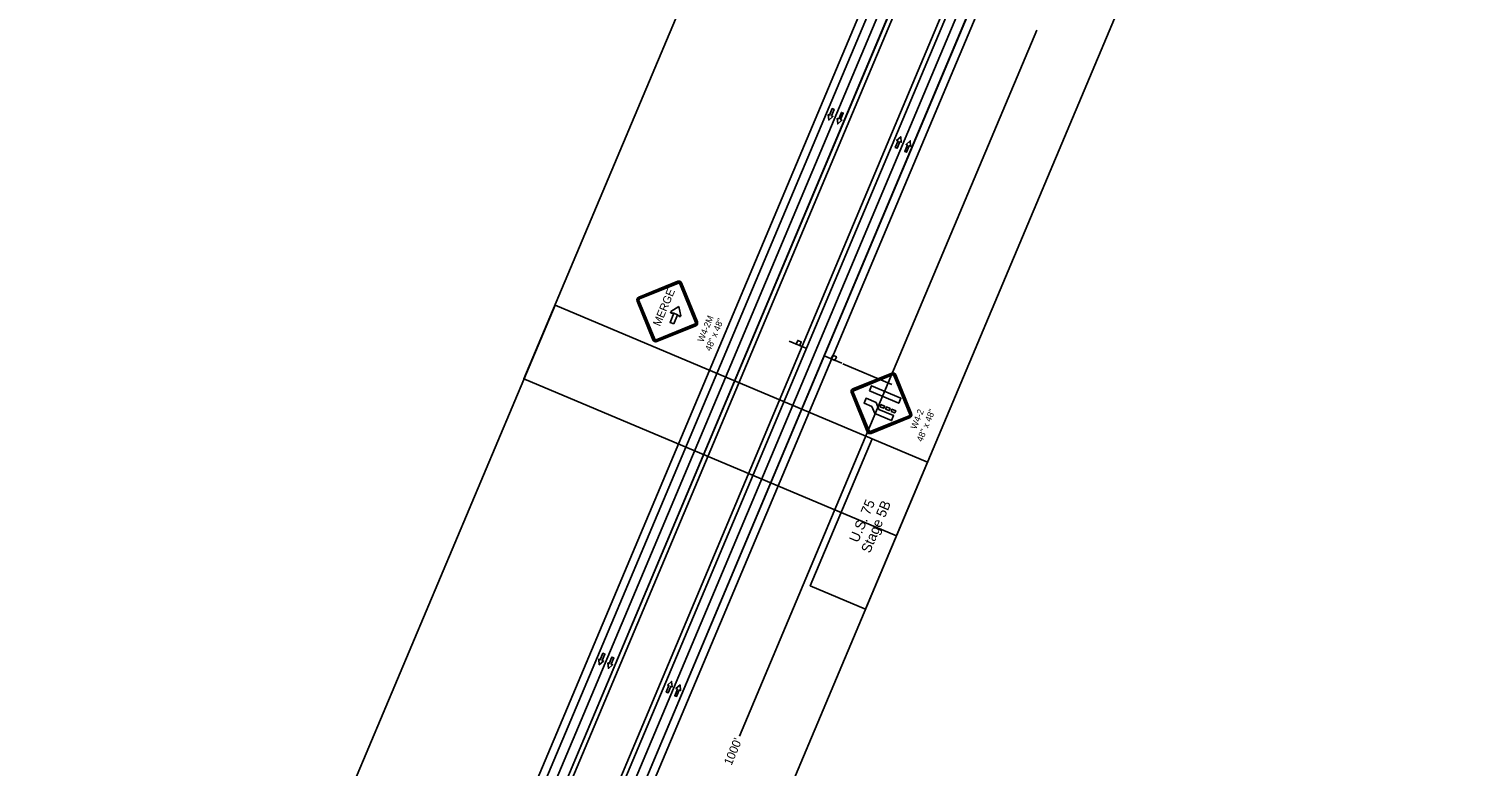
# Model space of a CAD drawing. Extents: x 14104283 to 14128447, y 8633203 to 8671666.
# Drawn here: x 14116868 to 14118675, y 8665326 to 8666247 of the extents above; entities that cross this region are included whole.
import ezdxf

# ---------------------------------------------------------------- set-up
doc = ezdxf.new("R2010")
doc.units = 0
for name, color, linetype in [('Cell', 7, 'Continuous'), ('Default', 7, 'Continuous'), ('dsnNonPlotable', 7, 'Continuous'), ('dsnPaintExistingBrokenLaneLineWhite', 7, 'Continuous'), ('dsnPaintExistingEdgeLineLeftYellow', 7, 'Continuous'), ('dsnPaintExistingEdgeLineRightWhite', 7, 'Continuous'), ('dsnShadingPaved', 7, 'Continuous'), ('dsnStdLabel', 7, 'Continuous'), ('dsnStgShadingPrevPav', 7, 'Continuous'), ('dsnTextOverlapEven', 7, 'Continuous')]:
    doc.layers.add(name, color=color, linetype=linetype)

msp = doc.modelspace()

# ---------------------------------------------------------------- linework, layer by layer
at = {"layer": 'Cell'}
for p, q in [((14117678.8, 8665931.5), (14117630.2, 8665911.7)), ((14117679.2, 8665930.6), (14117679.8, 8665929.2)), ((14117681.4, 8665928.5), (14117682.8, 8665929.1)), ((14117703.5, 8665880.8), (14117683.7, 8665929.4)), ((14117628.1, 8665906.8), (14117647.9, 8665858.2)), ((14117629, 8665907.2), (14117630.4, 8665907.7)), ((14117631.1, 8665909.4), (14117630.5, 8665910.8)), ((14117671, 8665892.7), (14117670.4, 8665893.6)), ((14117670.9, 8665891.7), (14117671, 8665892.7)), ((14117681.6, 8665888.3), (14117680.9, 8665887.5)), ((14117682.6, 8665888.4), (14117681.6, 8665888.3)), ((14117700.5, 8665878.2), (14117701.1, 8665876.8)), ((14117702.6, 8665880.5), (14117701.2, 8665879.9)), ((14117652.8, 8665856.1), (14117701.4, 8665875.9)), ((14117650.2, 8665859.1), (14117648.8, 8665858.5)), ((14117652.5, 8665857), (14117651.9, 8665858.4)), ((14117840.1, 8665847.4), (14117818, 8665856.7)), ((14117883.8, 8665829), (14117861.7, 8665838.3)), ((14117897.8, 8665797), (14117946.5, 8665816.8)), ((14117946.5, 8665816.8), (14117897.8, 8665797)), ((14117898.2, 8665796.2), (14117946.8, 8665816)), ((14117947.4, 8665814.5), (14117898.8, 8665794.7)), ((14117968.8, 8665765.2), (14117949, 8665813.8)), ((14117950.5, 8665814.4), (14117970.3, 8665765.8)), ((14117951.3, 8665814.8), (14117971.1, 8665766.2)), ((14117971.1, 8665766.2), (14117951.3, 8665814.8)), ((14117915.6, 8665743.5), (14117895.8, 8665792.2)), ((14117895.8, 8665792.2), (14117915.6, 8665743.5)), ((14117895.8, 8665792.2), (14117895.8, 8665792.2)), ((14117916.4, 8665743.9), (14117896.6, 8665792.5)), ((14117898.1, 8665793.1), (14117898.1, 8665793.1)), ((14117898.1, 8665793.1), (14117917.9, 8665744.5)), ((14117919.5, 8665743.8), (14117968.1, 8665763.6)), ((14117968.7, 8665762.1), (14117920.1, 8665742.3)), ((14117969.1, 8665761.3), (14117920.5, 8665741.5)), ((14117920.5, 8665741.5), (14117969.1, 8665761.3))]:
    msp.add_line(p, q, dxfattribs=at)
for points in [[(14117872, 8666147.3), (14117874.3, 8666146.3), (14117871, 8666138.2), (14117872.7, 8666137.5), (14117867.5, 8666132.9), (14117867, 8666139.9), (14117868.7, 8666139.2)], [(14117883.3, 8666142.5), (14117885.6, 8666141.6), (14117882.3, 8666133.5), (14117884, 8666132.7), (14117878.8, 8666128.2), (14117878.2, 8666135.1), (14117880, 8666134.4)], [(14117953.1, 8666097.8), (14117950.7, 8666098.7), (14117954.1, 8666106.8), (14117952.3, 8666107.6), (14117957.6, 8666112.1), (14117958.1, 8666105.2), (14117956.4, 8666105.9)], [(14117964.9, 8666092.8), (14117962.5, 8666093.8), (14117965.9, 8666101.9), (14117964.1, 8666102.6), (14117969.4, 8666107.2), (14117969.9, 8666100.2), (14117968.2, 8666100.9)], [(14117679.2, 8665930.6), (14117630.5, 8665910.8), (14117631.1, 8665909.4), (14117679.8, 8665929.2), (14117679.2, 8665930.6)], [(14117702.6, 8665880.5), (14117682.8, 8665929.1), (14117681.4, 8665928.5), (14117701.2, 8665879.9), (14117702.6, 8665880.5)], [(14117629, 8665907.2), (14117648.8, 8665858.5), (14117650.2, 8665859.1), (14117630.4, 8665907.7), (14117629, 8665907.2)], [(14117680.2, 8665899.9), (14117670.4, 8665893.6), (14117671, 8665892.7), (14117670.9, 8665891.7), (14117674, 8665891.5), (14117678.6, 8665889.6), (14117680.9, 8665887.5), (14117681.6, 8665888.3), (14117682.6, 8665888.4), (14117680.2, 8665899.9)], [(14117652.5, 8665857), (14117701.1, 8665876.8), (14117700.5, 8665878.2), (14117651.9, 8665858.4), (14117652.5, 8665857)], [(14117673.9, 8665878.3), (14117669.3, 8665880.2), (14117674, 8665891.5), (14117678.6, 8665889.6), (14117673.9, 8665878.3)], [(14117826.9, 8665853.1), (14117831.4, 8665851.1), (14117833.3, 8665855.7), (14117828.8, 8665857.6)], [(14117870.7, 8665834.6), (14117875.2, 8665832.7), (14117877.1, 8665837.2), (14117872.6, 8665839.1)], [(14117918.3, 8665794.6), (14117955.1, 8665779.1), (14117957.8, 8665785.3), (14117920.9, 8665800.9)], [(14117921.5, 8665775), (14117925, 8665766.3), (14117946, 8665757.4), (14117948.6, 8665763.7), (14117930.2, 8665771.4), (14117926.7, 8665780.1), (14117914.3, 8665785.3), (14117911.7, 8665779.1)], [(14117931.6, 8665774.8), (14117932.8, 8665777.5), (14117937.4, 8665775.6), (14117936.2, 8665772.8)], [(14117938.5, 8665771.9), (14117939.7, 8665774.6), (14117944.3, 8665772.7), (14117943.1, 8665769.9)], [(14117945.4, 8665769), (14117946.6, 8665771.7), (14117951.2, 8665769.8), (14117950, 8665767)], [(14117585.4, 8665466.8), (14117587.8, 8665465.8), (14117584.4, 8665457.8), (14117586.2, 8665457), (14117580.9, 8665452.4), (14117580.4, 8665459.4), (14117582.1, 8665458.7)], [(14117596.7, 8665462), (14117599, 8665461.1), (14117595.7, 8665453), (14117597.5, 8665452.3), (14117592.2, 8665447.7), (14117591.7, 8665454.7), (14117593.4, 8665453.9)], [(14117666.8, 8665417.2), (14117664.5, 8665418.2), (14117667.8, 8665426.3), (14117666.1, 8665427), (14117671.3, 8665431.6), (14117671.8, 8665424.6), (14117670.1, 8665425.3)], [(14117677.4, 8665412.8), (14117675.1, 8665413.7), (14117678.4, 8665421.8), (14117676.6, 8665422.5), (14117681.9, 8665427.1), (14117682.4, 8665420.1), (14117680.7, 8665420.8)]]:
    msp.add_lwpolyline(points, close=True, dxfattribs=at)
for points in [[(14117868.7, 8666139.2), (14117867, 8666139.9), (14117867.5, 8666132.9), (14117872.7, 8666137.5), (14117871, 8666138.2), (14117874.3, 8666146.3), (14117872, 8666147.3), (14117868.7, 8666139.2)], [(14117880, 8666134.4), (14117878.2, 8666135.1), (14117878.8, 8666128.2), (14117884, 8666132.7), (14117882.3, 8666133.5), (14117885.6, 8666141.6), (14117883.3, 8666142.5), (14117880, 8666134.4)], [(14117956.4, 8666105.9), (14117958.1, 8666105.2), (14117957.6, 8666112.1), (14117952.3, 8666107.6), (14117954.1, 8666106.8), (14117950.7, 8666098.7), (14117953.1, 8666097.8), (14117956.4, 8666105.9)], [(14117968.2, 8666100.9), (14117969.9, 8666100.2), (14117969.4, 8666107.2), (14117964.1, 8666102.6), (14117965.9, 8666101.9), (14117962.5, 8666093.8), (14117964.9, 8666092.8), (14117968.2, 8666100.9)], [(14117826.9, 8665853.1), (14117831.4, 8665851.1), (14117833.3, 8665855.7), (14117828.8, 8665857.6), (14117826.9, 8665853.1)], [(14117870.7, 8665834.6), (14117875.2, 8665832.7), (14117877.1, 8665837.2), (14117872.6, 8665839.1), (14117870.7, 8665834.6)], [(14117946.8, 8665816), (14117898.2, 8665796.2)], [(14117947.4, 8665814.5), (14117898.8, 8665794.7)], [(14117968.8, 8665765.2), (14117949, 8665813.8)], [(14117970.3, 8665765.8), (14117950.5, 8665814.4)], [(14117896.6, 8665792.5), (14117916.4, 8665743.9)], [(14117898.1, 8665793.1), (14117917.9, 8665744.5)], [(14117919.5, 8665743.8), (14117968.1, 8665763.6)], [(14117920.1, 8665742.3), (14117968.7, 8665762.1)], [(14117582.1, 8665458.7), (14117580.4, 8665459.4), (14117580.9, 8665452.4), (14117586.2, 8665457), (14117584.4, 8665457.8), (14117587.8, 8665465.8), (14117585.4, 8665466.8), (14117582.1, 8665458.7)], [(14117593.4, 8665453.9), (14117591.7, 8665454.7), (14117592.2, 8665447.7), (14117597.5, 8665452.3), (14117595.7, 8665453), (14117599, 8665461.1), (14117596.7, 8665462), (14117593.4, 8665453.9)], [(14117670.1, 8665425.3), (14117671.8, 8665424.6), (14117671.3, 8665431.6), (14117666.1, 8665427), (14117667.8, 8665426.3), (14117664.5, 8665418.2), (14117666.8, 8665417.2), (14117670.1, 8665425.3)], [(14117680.7, 8665420.8), (14117682.4, 8665420.1), (14117681.9, 8665427.1), (14117676.6, 8665422.5), (14117678.4, 8665421.8), (14117675.1, 8665413.7), (14117677.4, 8665412.8), (14117680.7, 8665420.8)]]:
    msp.add_lwpolyline(points, dxfattribs=at)
for centre, radius, start, end in [((14117680.2, 8665928), 3.75, 22.1549, 112.1545), ((14117680.2, 8665928), 2.81, 22.1549, 112.1545), ((14117680.2, 8665928), 1.25, 22.1549, 112.1545), ((14117631.6, 8665908.2), 3.75, 112.1547, 202.1544), ((14117631.6, 8665908.2), 2.81, 112.1547, 202.1544), ((14117631.6, 8665908.2), 1.25, 112.1547, 202.1544), ((14117671, 8665892.7), 1.02, 124.8424, 265.7361), ((14117681.6, 8665888.3), 1.02, 228.573, 9.4673), ((14117700, 8665879.4), 1.25, 292.1547, 22.1549), ((14117700, 8665879.4), 2.81, 292.1547, 22.1549), ((14117700, 8665879.4), 3.75, 292.1547, 22.1549), ((14117651.4, 8665859.6), 3.75, 202.1544, 292.1547), ((14117651.4, 8665859.6), 2.81, 202.1544, 292.1547), ((14117651.4, 8665859.6), 1.25, 202.1544, 292.1547), ((14117947.9, 8665813.4), 3.75, 22.1547, 112.155), ((14117947.9, 8665813.4), 3.75, 22.1547, 112.155), ((14117947.9, 8665813.4), 2.81, 22.1547, 112.155), ((14117947.9, 8665813.4), 2.81, 22.1547, 112.155), ((14117947.9, 8665813.4), 1.25, 22.1547, 112.155), ((14117947.9, 8665813.4), 1.25, 22.1547, 112.155), ((14117899.2, 8665793.6), 3.75, 112.155, 202.1547), ((14117899.2, 8665793.6), 3.75, 112.155, 202.1547), ((14117899.2, 8665793.6), 2.81, 112.155, 202.1547), ((14117899.2, 8665793.6), 2.81, 112.155, 202.1547), ((14117899.2, 8665793.6), 1.25, 112.155, 202.1547), ((14117899.2, 8665793.6), 1.25, 112.155, 202.1547), ((14117967.7, 8665764.7), 1.25, 292.1545, 22.1547), ((14117967.7, 8665764.7), 1.25, 292.1545, 22.1547), ((14117967.7, 8665764.7), 2.81, 292.1545, 22.1547), ((14117967.7, 8665764.7), 2.81, 292.1545, 22.1547), ((14117967.7, 8665764.7), 3.75, 292.1545, 22.1547), ((14117967.7, 8665764.7), 3.75, 292.1545, 22.1547), ((14117919, 8665744.9), 3.75, 202.1549, 292.1545), ((14117919, 8665744.9), 3.75, 202.1549, 292.1545), ((14117919, 8665744.9), 2.81, 202.1549, 292.1545), ((14117919, 8665744.9), 2.81, 202.1549, 292.1545), ((14117919, 8665744.9), 1.25, 202.1549, 292.1545), ((14117919, 8665744.9), 1.25, 202.1549, 292.1545)]:
    msp.add_arc(centre, radius, start, end, dxfattribs=at)
at = {"layer": 'Default'}
for points in [[(14118413.2, 8667444.3), (14110818.4, 8649409.2), (14109142.6, 8645431.4)], [(14109164.7, 8645422.1), (14110840.5, 8649399.8), (14118435.4, 8667434.9)]]:
    msp.add_lwpolyline(points, dxfattribs=at)
at = {"layer": 'dsnNonPlotable'}
for points in [[(14117486.7, 8665809.5), (14118095.3, 8667254.1), (14118560.7, 8667058), (14117952.1, 8665613.5)], [(14116917, 8664457.1), (14117525.6, 8665901.7), (14117990.9, 8665705.6), (14117382.4, 8664261.1)]]:
    msp.add_lwpolyline(points, close=True, dxfattribs=at)
at = {"layer": 'dsnPaintExistingBrokenLaneLineWhite'}
for p, q in [((14114932.5, 8658913.4), (14118537.6, 8667474.2)), ((14110829.5, 8649404.5), (14118424.3, 8667439.6))]:
    msp.add_line(p, q, dxfattribs=at)
at = {"layer": 'dsnPaintExistingEdgeLineLeftYellow'}
for p, q in [((14115900.9, 8661244), (14118759.4, 8668031.7)), ((14118435.4, 8667434.9), (14115816.1, 8661215.2))]:
    msp.add_line(p, q, dxfattribs=at)
at = {"layer": 'dsnPaintExistingEdgeLineRightWhite'}
for p, q in [((14110924.4, 8649364.5), (14118874.7, 8668243.7)), ((14118413.2, 8667444.3), (14115798.8, 8661235.7))]:
    msp.add_line(p, q, dxfattribs=at)
at = {"layer": 'dsnShadingPaved'}
for p, q in [((14115901.2, 8661244.5), (14118227.7, 8666769.2)), ((14118249.8, 8666759.9), (14115923.3, 8661235.2))]:
    msp.add_line(p, q, dxfattribs=at)
at = {"layer": 'dsnStdLabel'}
for p, q in [((14118127.5, 8666245.3), (14117941.9, 8665804.6)), ((14117946.5, 8665802.6), (14117885.2, 8665828.4)), ((14117941.9, 8665804.6), (14117755.9, 8665363.1))]:
    msp.add_line(p, q, dxfattribs=at)
at = {"layer": 'dsnStgShadingPrevPav'}
for p, q in [((14115895.6, 8661246.8), (14118811.5, 8668171)), ((14118848.4, 8668155.5), (14115932.5, 8661231.3)), ((14118653, 8668013.6), (14115794, 8661224.5)), ((14115816.1, 8661215.2), (14118675.1, 8668004.3)), ((14115816.1, 8661215.2), (14118675.1, 8668004.3)), ((14118680.7, 8668002), (14115821.7, 8661212.9)), ((14110809.2, 8649413), (14118404, 8667448.1)), ((14118413.2, 8667444.3), (14110818.4, 8649409.2))]:
    msp.add_line(p, q, dxfattribs=at)
at = {"layer": 'dsnTextOverlapEven'}
for points in [[(14117990.9, 8665705.6), (14117913.6, 8665522), (14117844.5, 8665551.1), (14117921.8, 8665734.7)], [(14117844.5, 8665551.1), (14117921.8, 8665734.7), (14117990.9, 8665705.6), (14117913.6, 8665522)]]:
    msp.add_lwpolyline(points, close=True, dxfattribs=at)

# ---------------------------------------------------------------- texts
at = {"layer": 'Cell'}
for s, height, p in [('MERGE', 10, (14117656.7, 8665874.5)), ('W4-2M', 8, (14117710.6, 8665854.8)), ('48" x 48"', 8, (14117720, 8665843.6)), ('W4-2', 8, (14117976.8, 8665745.9)), ('48" x 48"', 8, (14117984.3, 8665730.3))]:
    msp.add_text(s, height=height, rotation=67.1547, dxfattribs=at).set_placement(p)
at = {"layer": 'dsnStdLabel'}
msp.add_text("1000'", height=10.8, rotation=67.1547, dxfattribs=at).set_placement((14117746, 8665325.8))
at = {"layer": 'dsnTextOverlapEven'}
for s, p in [('U.S. 75', (14117904.1, 8665604.1)), ('Stage 5B', (14117918.9, 8665590.9))]:
    msp.add_text(s, height=12.5, rotation=67.1547, dxfattribs=at).set_placement(p)

doc.saveas('drawing.dxf')
